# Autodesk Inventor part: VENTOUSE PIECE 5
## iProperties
Created: 2004-11
Part Number: VENTOUSE PIECE 5
Document SubType Name: Modeling
Designer: Bruno
Manufacturer: Standard
Standards Organization: Custom
Author: Bruno
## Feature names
1. Base1
